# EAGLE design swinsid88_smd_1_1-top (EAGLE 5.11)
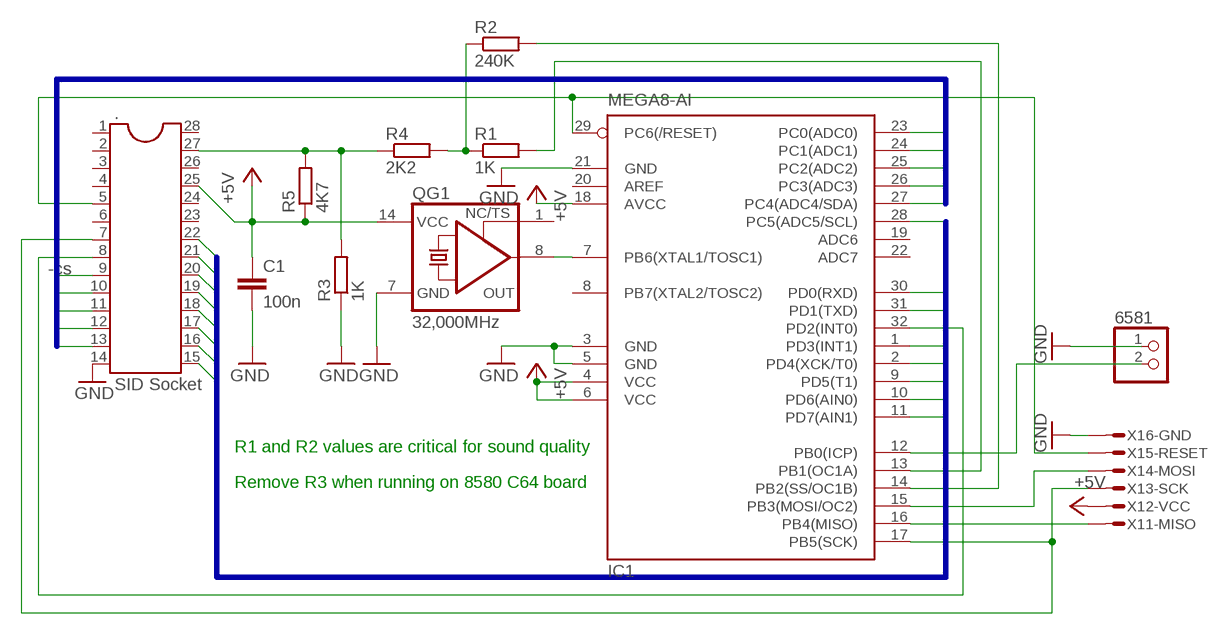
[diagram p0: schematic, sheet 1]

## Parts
6581  PINHD-1X02_2.00  [1X02M]
.  SID Socket  DIL28  [DIL28-6]
C1  100n  C-EU025-024X044  [C025-024X044]
IC1  MEGA8-AI  [TQFP32-08]
QG1  32,000MHz  XO-14  [DIL14S]
R1  1K  R-EU_R1206  [R1206]
R2  240K  R-EU_R1206  [R1206]
R3  1K  R-EU_R1206  [R1206]
R4  2K2  R-EU_R1206  [R1206]
R5  4K7  R-EU_R1206  [R1206]
X1  AVR-ISP_1X6  [1X6_ISP]

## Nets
+5V: ..25 C1.1 IC1.4(VCC) IC1.6(VCC) IC1.18(AVCC) QG1.14(VCC) R5.1 X1.2
A0: ..9 IC1.23(PC0(ADC0))
A1: ..10 IC1.24(PC1(ADC1))
A2: ..11 IC1.25(PC2(ADC2))
A3: ..12 IC1.26(PC3(ADC3))
A4: ..13 IC1.27(PC4(ADC4/SDA))
D0: ..15 IC1.30(PD0(RXD))
D1: ..16 IC1.31(PD1(TXD))
D2: ..17 IC1.28(PC5(ADC5/SCL))
D3: ..18 IC1.1(PD3(INT1))
D4: ..19 IC1.2(PD4(XCK/T0))
D5: ..20 IC1.9(PD5(T1))
D6: ..21 IC1.10(PD6(AIN0))
D7: ..22 IC1.11(PD7(AIN1))
GND: 6581.1 ..14 C1.2 IC1.3(GND) IC1.5(GND) IC1.21(GND) QG1.7(GND) R3.1 X1.6
N$1: IC1.7(PB6(XTAL1/TOSC1)) QG1.8(OUT)
N$2: ..27 R3.2 R4.1 R5.2
N$3: R1.1 R2.1 R4.2
N$4: IC1.16(PB4(MISO)) X1.1
N$5: ..7 IC1.17(PB5(SCK)) X1.3
N$6: IC1.13(PB1(OC1A)) R1.2
N$7: IC1.14(PB2(SS/OC1B)) R2.2
N$8: IC1.15(PB3(MOSI/OC2)) X1.4
N$9: 6581.2 IC1.12(PB0(ICP))
N$11: ..8 IC1.32(PD2(INT0))
P5: ..5 IC1.29(PC6(/RESET)) X1.5
Unconnected: ..1 ..2 ..3 ..4 ..6 ..23 ..24 ..26 ..28 IC1.8(PB7(XTAL2/TOSC2)) IC1.19(ADC6) IC1.20(AREF) IC1.22(ADC7) QG1.1(TS)

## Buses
DATA:D7,D6,D5,D4,D3,D2,D1,D0
ADR:A0,A1,A2,A3,A4

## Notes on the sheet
- -cs
- R1 and R2 values are critical for sound quality
- Remove R3 when running on 8580 C64 board

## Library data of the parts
6581 = pinhead-2:PINHD-1X02: PIN HEADER
. = ic-package:DIL28: Dual In Line
C1 = rcl:C-EU: CAPACITOR, European symbol
IC1 = atmel:MEGA8: MICROCONTROLLER 8 Kbytes FLASH, 1 kbytes SRAM, 512 bytes EEPROM, USART, 6-channel 10 bit ADC, 2-channel 8 bit ADC Pin compatible with Atmega48, ATMega88, ATMega168 Source: avr.lbr; MPN: ATMEGA8-16AU; OC_FARNELL: 9171371; OC_NEWARK: 73M8863
QG1 = crystal:XO-: CRYSTAL; OC_FARNELL: unknown; OC_NEWARK: unknown
R1-R5 = rcl:R-EU_: RESISTOR, European symbol
X1 = 0_rr:AVR-ISP: MicroMaTch 6 7-215464-6 / 0-215464-6 Drawing Number C-215464 DDEController.pdf

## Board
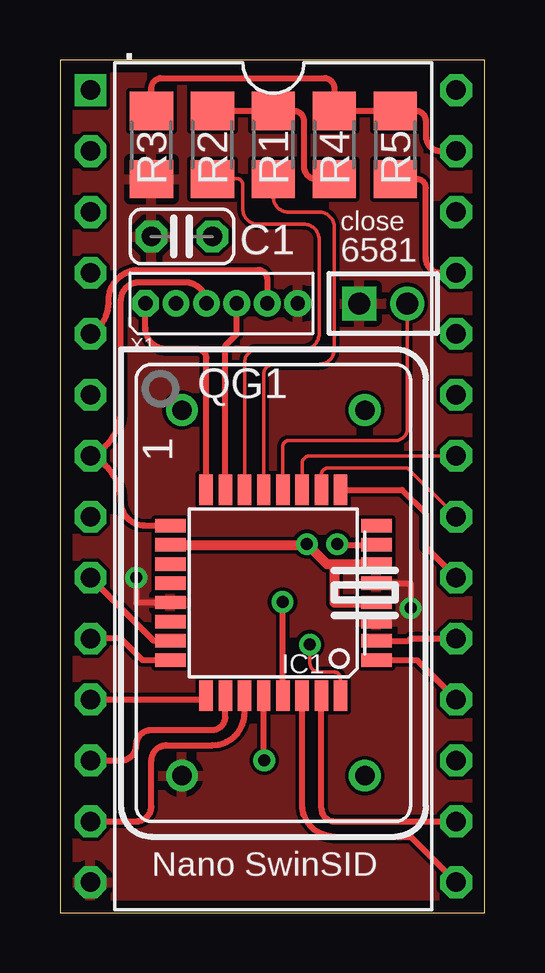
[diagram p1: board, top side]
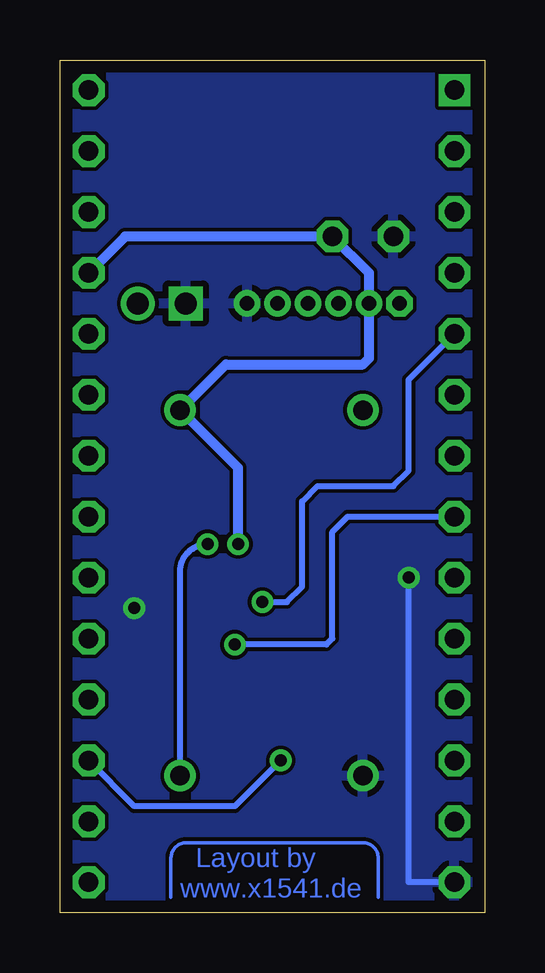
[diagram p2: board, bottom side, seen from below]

Size 17.7 x 35.55 mm. Coordinates in mm from the lower left corner, seen from the top.
Outline: 0,0 17.7,0 17.7,35.55 0,35.55 0,0
Copper layers (1*16): Top 0.035mm / dielectric 1.5mm / Bottom 0.035mm
Design rules "default *": minimum track width 6mil, minimum drill 12mil, track to track 6mil, track to pad 6mil, pad to pad 6mil, via to via 6mil, smd to smd 6mil, copper to edge 20mil, drill to drill 8mil, minimum pad ring 10mil, minimum via ring 8mil, stop-mask expansion 4mil, vias tented up to drill 0mil, thermal gap 10mil

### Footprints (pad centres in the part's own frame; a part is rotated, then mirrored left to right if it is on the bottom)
1X02M = drill 0.914 square: 1 -1,0 | drill 0.914 round: 2 1,0
DIL28-6 = drill 0.813 square: 1 -16.51,-7.62 | drill 0.813 octagon: 2 -13.97,-7.62; 3 -11.43,-7.62; 4 -8.89,-7.62; 5 -6.35,-7.62; 6 -3.81,-7.62; 7 -1.27,-7.62; 8 1.27,-7.62; 9 3.81,-7.62; 10 6.35,-7.62; 11 8.89,-7.62; 12 11.43,-7.62; 13 13.97,-7.62; 14 16.51,-7.62; 15 16.51,7.62; 16 13.97,7.62; 17 11.43,7.62; 18 8.89,7.62; 19 6.35,7.62; 20 3.81,7.62; 21 1.27,7.62; 22 -1.27,7.62; 23 -3.81,7.62; 24 -6.35,7.62; 25 -8.89,7.62; 26 -11.43,7.62; 27 -13.97,7.62; 28 -16.51,7.62
C025-024X044 = drill 0.813 octagon: 1 -1.27,0; 2 1.27,0
TQFP32-08 = smd 1.27 x 0.559: 1 -4.293,2.8; 2 -4.293,2; 3 -4.293,1.2; 4 -4.293,0.4; 5 -4.293,-0.4; 6 -4.293,-1.2; 7 -4.293,-2; 8 -4.293,-2.8; 17 4.293,-2.8; 18 4.293,-2; 19 4.293,-1.2; 20 4.293,-0.4; 21 4.293,0.4; 22 4.293,1.2; 23 4.293,2; 24 4.293,2.8 | smd 0.559 x 1.27: 9 -2.8,-4.293; 10 -2,-4.293; 11 -1.2,-4.293; 12 -0.4,-4.293; 13 0.4,-4.293; 14 1.2,-4.293; 15 2,-4.293; 16 2.8,-4.293; 25 2.8,4.293; 26 2,4.293; 27 1.2,4.293; 28 0.4,4.293; 29 -0.4,4.293; 30 -1.2,4.293; 31 -2,4.293; 32 -2.8,4.293
DIL14S = drill 0.813 round: 1 -7.62,-3.81; 7 7.62,-3.81; 8 7.62,3.81; 14 -7.62,3.81
R1206 = smd 1.6 x 1.803: 1 -1.422,0; 2 1.422,0
1X6_ISP = drill 0.6 pad 0.94 octagon: 1 0,0 | drill 0.6 pad 0.94 round: 2 1.27,0; 3 2.54,0; 4 3.81,0; 5 5.08,0; 6 6.35,0

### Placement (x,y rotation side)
6581  13.46,25.4 0 top
.  8.89,17.78 270 top
C1  5.08,28.19 180 top
IC1  8.89,13.33 180 top
QG1  8.89,13.33 270 top
R1  8.89,32 270 top
R2  6.35,32 270 top
R3  3.81,32 90 top
R4  11.43,32 270 top
R5  13.97,32 90 top
X1  3.56,25.4 0 top

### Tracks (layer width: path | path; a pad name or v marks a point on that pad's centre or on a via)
+5V  (via drill 0.5)
  Top 0.254: 10.25,15.33 v10.29,15.37 | R5.1 14.88,30.58 arc-90 15.24,30.23 15.24,27.3 arc90 15.88,26.67 ..25
  Top 0.406: IC1.4 11.43,12.94 11.43,14.53 | IC1.18 10.25,15.33 | 11.43,14.53 IC1.6 | 11.43,14.53 11.12,14.53 v10.29,15.37
  Bottom 0.406: ..25 14.99,28.19 C1.1 4.83,26.67 X1.2 4.83,23.11 5.08,22.86 10.79,22.86 QG1.14 10.29,18.54 v10.29,15.37
A0
  Top 0.254: IC1.23 3.9,11.33 ..9
A1
  Top 0.254: IC1.24 3.43,10.54 2.54,11.43 ..10
A2
  Top 0.254: ..11 5.94,8.89 IC1.25
A3
  Top 0.254: IC1.26 6.89,8.16 arc-90 6.35,7.62 3.81,7.62 arc90 3.17,6.98 arc-90 2.54,6.35 ..12
A4
  Top 0.254: IC1.27 7.69,8.32 arc-90 6.35,6.98 4.45,6.98 arc90 3.81,6.35 3.81,4.45 arc-90 3.17,3.81 ..13
D0
  Top 0.254: IC1.30 10.09,4.51 arc90 11.43,3.18 14.61,3.18 ..15
D1
  Top 0.254: IC1.31 10.89,4.35 arc90 11.43,3.81 ..16
D2  (via drill 0.5)
  Top 0.254: IC1.28 8.49,6.75 v8.51,6.35
  Bottom 0.254: ..17 14.61,4.45 10.41,4.45 v8.51,6.35
D3
  Top 0.254: IC1.1 14.86,10.54 ..18
D4
  Top 0.254: IC1.2 14.51,11.33 14.61,11.43 ..19
D5
  Top 0.254: IC1.9 14.25,17.63 15.24,16.64 15.24,15.24 ..20
D6
  Top 0.152: ..21 14.48,18.54 11.18,18.54 arc90 10.89,18.26 IC1.10
D7
  Top 0.152: IC1.11 10.09,18.73 arc-90 10.41,19.05 ..22
GND  (via drill 0.5)
  Top 0.254: IC1.5 14.61,13.74 v14.61,12.7 | IC1.21 3.17,12.94 v3.17,13.97
  Bottom 0.254: v3.17,13.97 3.17,1.27 ..14
  pour Top: 0,35.56 17.78,35.56 17.78,0 0,0
  pour Bottom: 0,35.56 17.78,35.56 17.78,0 0,0
N$1  (via drill 0.5)
  Top 0.254: IC1.7 11.59,15.33 v11.56,15.37
  Bottom 0.254: QG1.8 12.7,14.22 arc90 v11.56,15.37
N$2
  Top 0.152: R5.2 14.83,33.43
  Top 0.254: 13.82,33.81 R5.2 R4.1 11.43,34.29 arc90 11.05,34.8 4.19,34.8 arc90 3.81,34.29 R3.2 | 14.83,33.43 arc-90 15.24,33.02 15.24,32.38 arc90 15.88,31.75 ..27
N$3
  Top 0.254: R2.1 R1.1 9.75,33.43 arc-90 10.16,33.02 10.16,31.11 arc90 10.69,30.58 R4.2
N$4
  Top 0.254: X1.1 3.56,24.38 arc90 4.45,23.5 5.71,23.5 arc-90 6.1,23.11 IC1.16 arc-90 IC1.16
N$5
  Top 0.254: IC1.17 3.55,16.14 arc-90 2.54,17.14 arc67 ..7 arc67 2.54,20.96 2.54,25.53 arc-90 3.3,26.29 5.21,26.29 arc-90 X1.3
N$6
  Top 0.152: 8.91,30.61 R1.2 8.89,29.85 arc90 9.52,29.21 10.79,29.21 arc-90 11.43,28.57 11.43,23.5 arc-90 10.79,22.86 8.89,22.86 arc90 8.49,22.46 IC1.13
N$7
  Top 0.152: R2.2 6.38,30.61 7.37,30.61 arc-90 7.62,30.35 7.62,29.34 arc90 8.25,28.7 10.16,28.7 arc-90 10.79,28.07 10.79,24.13 arc-90 10.16,23.5 8.25,23.5 arc90 7.69,22.93 IC1.14
N$8
  Top 0.254: IC1.15 6.89,23.65 7.37,24.13 X1.4
N$9
  Top 0.152: IC1.12 9.29,19.45 arc-90 9.52,19.69 13.97,19.69 arc90 14.48,20.19 14.48,25.51
  Top 0.254: 14.48,25.51 6581.2
N$10
  Bottom 0.152: 4.45,0.64 4.45,2.29 arc-90 5.08,2.92 12.45,2.92 arc-90 13.08,2.29 13.08,0.64
N$11  (via drill 0.5)
  Top 0.152: IC1.32 IC1.32 arc-90 IC1.32 | v10.41,11.18 10.41,10.41 arc90 10.79,10.03 11.43,10.03 arc-90 11.68,9.78 IC1.32
  Bottom 0.254: v10.41,11.18 6.6,11.18 6.35,11.43 6.35,15.87 5.71,16.51 ..8
P5  (via drill 0.5)
  Top 0.254: IC1.29 9.27,9.04 v9.27,12.95 | X1.5 8.64,26.42 arc90 8.25,26.8 3.17,26.8 arc90 2.03,25.4 arc-57 ..5
  Bottom 0.254: ..5 3.17,22.23 3.17,18.42 3.81,17.78 6.98,17.78 7.62,17.14 7.62,13.59 8.25,12.95 v9.27,12.95

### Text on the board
Bottom: Layout by | www.x1541.de
tNames: close | Nano SwinSID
